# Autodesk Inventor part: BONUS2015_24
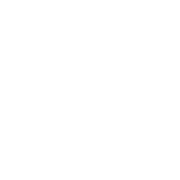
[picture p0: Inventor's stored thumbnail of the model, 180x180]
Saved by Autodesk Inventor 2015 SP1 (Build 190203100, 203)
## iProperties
Created: 2015-05
Part Number: BONUS2015_24
Material: Generisch
Document SubType Name: Modeling
Density: 1 g/cm^3
Appearance: Vorgabe
xx: 24
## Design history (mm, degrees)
